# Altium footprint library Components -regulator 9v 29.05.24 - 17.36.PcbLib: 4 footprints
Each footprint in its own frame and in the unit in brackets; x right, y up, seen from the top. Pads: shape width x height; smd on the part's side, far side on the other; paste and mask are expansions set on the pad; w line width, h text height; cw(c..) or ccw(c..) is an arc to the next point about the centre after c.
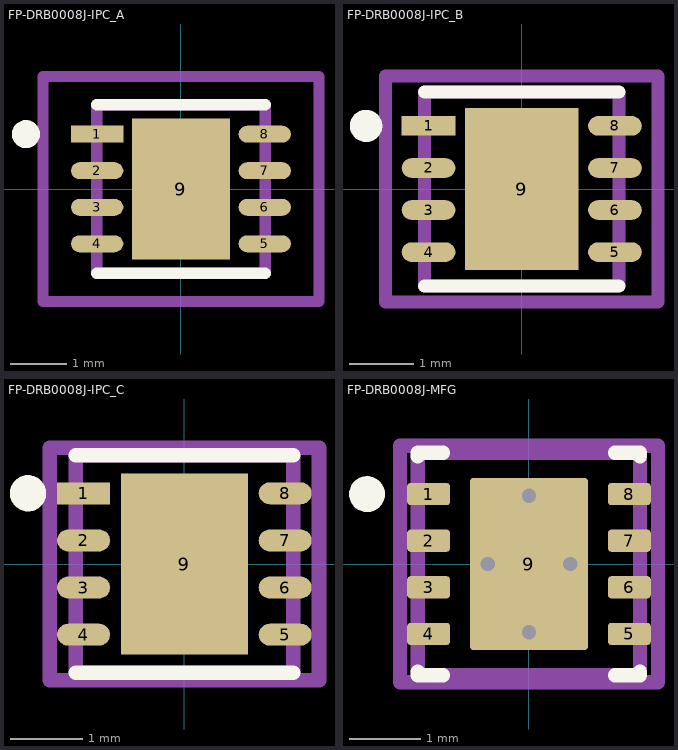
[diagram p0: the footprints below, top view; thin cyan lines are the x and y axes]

## FP-DRB0008J-IPC_A [mm]
pads (9):
  rect 0.931x0.302 smd paste+0 mask+0: 1(-1.491,0.975)
  rrect100% 0.931x0.302 smd paste+0 mask+0: 2(-1.491,0.325) 3(-1.491,-0.325) 4(-1.491,-0.975) 5(1.491,-0.975) 6(1.491,-0.325) 7(1.491,0.325) 8(1.491,0.975)
  rect 1.75x2.5 smd paste-1000 mask+0: 9(0,0)
Top Overlay:
  circle w0.25: c-2.756,0.975 r0.125
  lines w0.2: -1.5,-1.5 -1.5,-1.5 ; -1.5,-1.5 1.5,-1.5 ; -1.5,1.5 -1.5,1.5 ; -1.5,1.5 1.5,1.5 ; 1.5,-1.5 1.5,-1.5 ; 1.5,1.5 1.5,1.5
Top Paste:
  rectangle: -0.5,-0.875 0.5,0.875
Top Assembly:
  lines w0.2: -2.456,-2 2.456,-2 2.456,2 -2.456,2 -2.456,-2
  text ".Designator" at 0,-0.001 h1
Top 3D Body:
  lines w0.2: -1.5,-1.5 1.5,-1.5 1.5,1.5 -1.5,1.5 -1.5,-1.5
Top Courtyard:
  lines w0.2: -2.456,-2 2.456,-2 2.456,2 -2.456,2 -2.456,-2
Top Component Center:
  lines w0.1: -0.5,0 0.5,0 ; 0,-0.5 0,0.5
3D body "IC_Texas_Instruments_TLV76601QWDRBRQ1_eec.STEP": height 0.25, standoff 0, extent -2.456,-2 2.456,2

## FP-DRB0008J-IPC_B [mm]
pads (9):
  rect 0.831x0.302 smd paste+0 mask+0: 1(-1.441,0.975)
  rrect100% 0.831x0.302 smd paste+0 mask+0: 2(-1.441,0.325) 3(-1.441,-0.325) 4(-1.441,-0.975) 5(1.441,-0.975) 6(1.441,-0.325) 7(1.441,0.325) 8(1.441,0.975)
  rect 1.75x2.5 smd paste-1000 mask+0: 9(0,0)
Top Overlay:
  circle w0.25: c-2.406,0.975 r0.125
  lines w0.2: -1.5,-1.5 -1.5,-1.5 ; -1.5,-1.5 1.5,-1.5 ; -1.5,1.5 -1.5,1.5 ; -1.5,1.5 1.5,1.5 ; 1.5,-1.5 1.5,-1.5 ; 1.5,1.5 1.5,1.5
Top Paste:
  rectangle: -0.5,-0.875 0.5,0.875
Top Assembly:
  lines w0.2: -2.106,-1.75 2.106,-1.75 2.106,1.75 -2.106,1.75 -2.106,-1.75
  text ".Designator" at 0,-0.001 h1
Top 3D Body:
  lines w0.2: -1.5,-1.5 1.5,-1.5 1.5,1.5 -1.5,1.5 -1.5,-1.5
Top Courtyard:
  lines w0.2: -2.106,-1.75 2.106,-1.75 2.106,1.75 -2.106,1.75 -2.106,-1.75
Top Component Center:
  lines w0.1: -0.5,0 0.5,0 ; 0,-0.5 0,0.5
3D body "IC_Texas_Instruments_TLV76601QWDRBRQ1_eec.STEP": height 0.25, standoff 0, extent -2.106,-1.75 2.106,1.75

## FP-DRB0008J-IPC_C [mm]
pads (9):
  rect 0.731x0.302 smd paste+0 mask+0: 1(-1.391,0.975)
  rrect100% 0.731x0.302 smd paste+0 mask+0: 2(-1.391,0.325) 3(-1.391,-0.325) 4(-1.391,-0.975) 5(1.391,-0.975) 6(1.391,-0.325) 7(1.391,0.325) 8(1.391,0.975)
  rect 1.75x2.5 smd paste-1000 mask+0: 9(0,0)
Top Overlay:
  circle w0.25: c-2.156,0.975 r0.125
  lines w0.2: -1.5,-1.5 -1.5,-1.5 ; -1.5,-1.5 1.5,-1.5 ; -1.5,1.5 -1.5,1.5 ; -1.5,1.5 1.5,1.5 ; 1.5,-1.5 1.5,-1.5 ; 1.5,1.5 1.5,1.5
Top Paste:
  rectangle: -0.5,-0.875 0.5,0.875
Top Assembly:
  lines w0.2: -1.856,-1.6 1.856,-1.6 1.856,1.6 -1.856,1.6 -1.856,-1.6
  text ".Designator" at 0,-0.001 h1
Top 3D Body:
  lines w0.2: -1.5,-1.5 1.5,-1.5 1.5,1.5 -1.5,1.5 -1.5,-1.5
Top Courtyard:
  lines w0.2: -1.856,-1.6 1.856,-1.6 1.856,1.6 -1.856,1.6 -1.856,-1.6
Top Component Center:
  lines w0.1: -0.5,0 0.5,0 ; 0,-0.5 0,0.5
3D body "IC_Texas_Instruments_TLV76601QWDRBRQ1_eec.STEP": height 0.25, standoff 0, extent -1.856,-1.6 1.856,1.6

## FP-DRB0008J-MFG [mm]
pads (9):
  rrect32% 0.6x0.31 smd paste+0 mask+0: 1(-1.4,0.975) 2(-1.4,0.325) 3(-1.4,-0.325) 4(-1.4,-0.975) 5(1.4,-0.975) 6(1.4,-0.325) 7(1.4,0.325) 8(1.4,0.975)
  rrect6% 1.65x2.4 smd paste-1000 mask+0: 9(0,0)
via -0.575,0 diameter 0.5 hole 0.2
via 0.575,0 diameter 0.5 hole 0.2
via 0,0.95 diameter 0.5 hole 0.2
via 0,-0.95 diameter 0.5 hole 0.2
Top Overlay:
  circle w0.25: c-2.26,0.975 r0.125
  lines w0.2: -1.55,-1.505 -1.55,-1.55 -1.2,-1.55 ; -1.55,1.505 -1.55,1.55 -1.2,1.55 ; 1.2,-1.55 1.55,-1.55 1.55,-1.505 ; 1.2,1.55 1.55,1.55 1.55,1.505
Top Paste:
  region: -0.705,1.16 0.705,1.16 0.715,1.16 0.733,1.152 0.747,1.138 0.755,1.12 0.755,1.11 0.755,0.15 0.755,0.14 0.747,0.122 0.733,0.108 0.715,0.1 0.705,0.1 -0.705,0.1 -0.715,0.1 -0.733,0.108 -0.747,0.122 -0.755,0.14 -0.755,0.15 -0.755,1.11 -0.755,1.12 -0.747,1.138 -0.733,1.152 -0.715,1.16
  region: -0.755,-0.15 -0.755,-0.14 -0.747,-0.122 -0.733,-0.108 -0.715,-0.1 -0.705,-0.1 0.705,-0.1 0.715,-0.1 0.733,-0.108 0.747,-0.122 0.755,-0.14 0.755,-0.15 0.755,-1.11 0.755,-1.12 0.747,-1.138 0.733,-1.152 0.715,-1.16 0.705,-1.16 -0.705,-1.16 -0.715,-1.16 -0.733,-1.152 -0.747,-1.138 -0.755,-1.12 -0.755,-1.11
Top Assembly:
  lines w0.2: -1.8,-1.65 1.8,-1.65 1.8,1.65 -1.8,1.65 -1.8,-1.65
  text ".Designator" at 0,0.188 h1
Top 3D Body:
  lines w0.2: -1.55,-1.55 1.55,-1.55 1.55,1.55 -1.55,1.55 -1.55,-1.55
Top Courtyard:
  lines w0.2: -1.8,-1.65 1.8,-1.65 1.8,1.65 -1.8,1.65 -1.8,-1.65
Top Component Center:
  lines w0.1: -0.5,0 0.5,0 ; 0,-0.5 0,0.5
3D body "IC_Texas_Instruments_TLV76601QWDRBRQ1_eec.STEP": height 0.25, standoff 0, extent -1.8,-1.65 1.8,1.65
